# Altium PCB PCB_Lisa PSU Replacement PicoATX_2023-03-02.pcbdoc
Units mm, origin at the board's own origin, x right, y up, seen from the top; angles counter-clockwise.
Board outline 280.87 x 238.64 mm, 2 copper layers (Top Layer, Bottom Layer); 64 components, 40 nets, 167 pads, 1 vias.
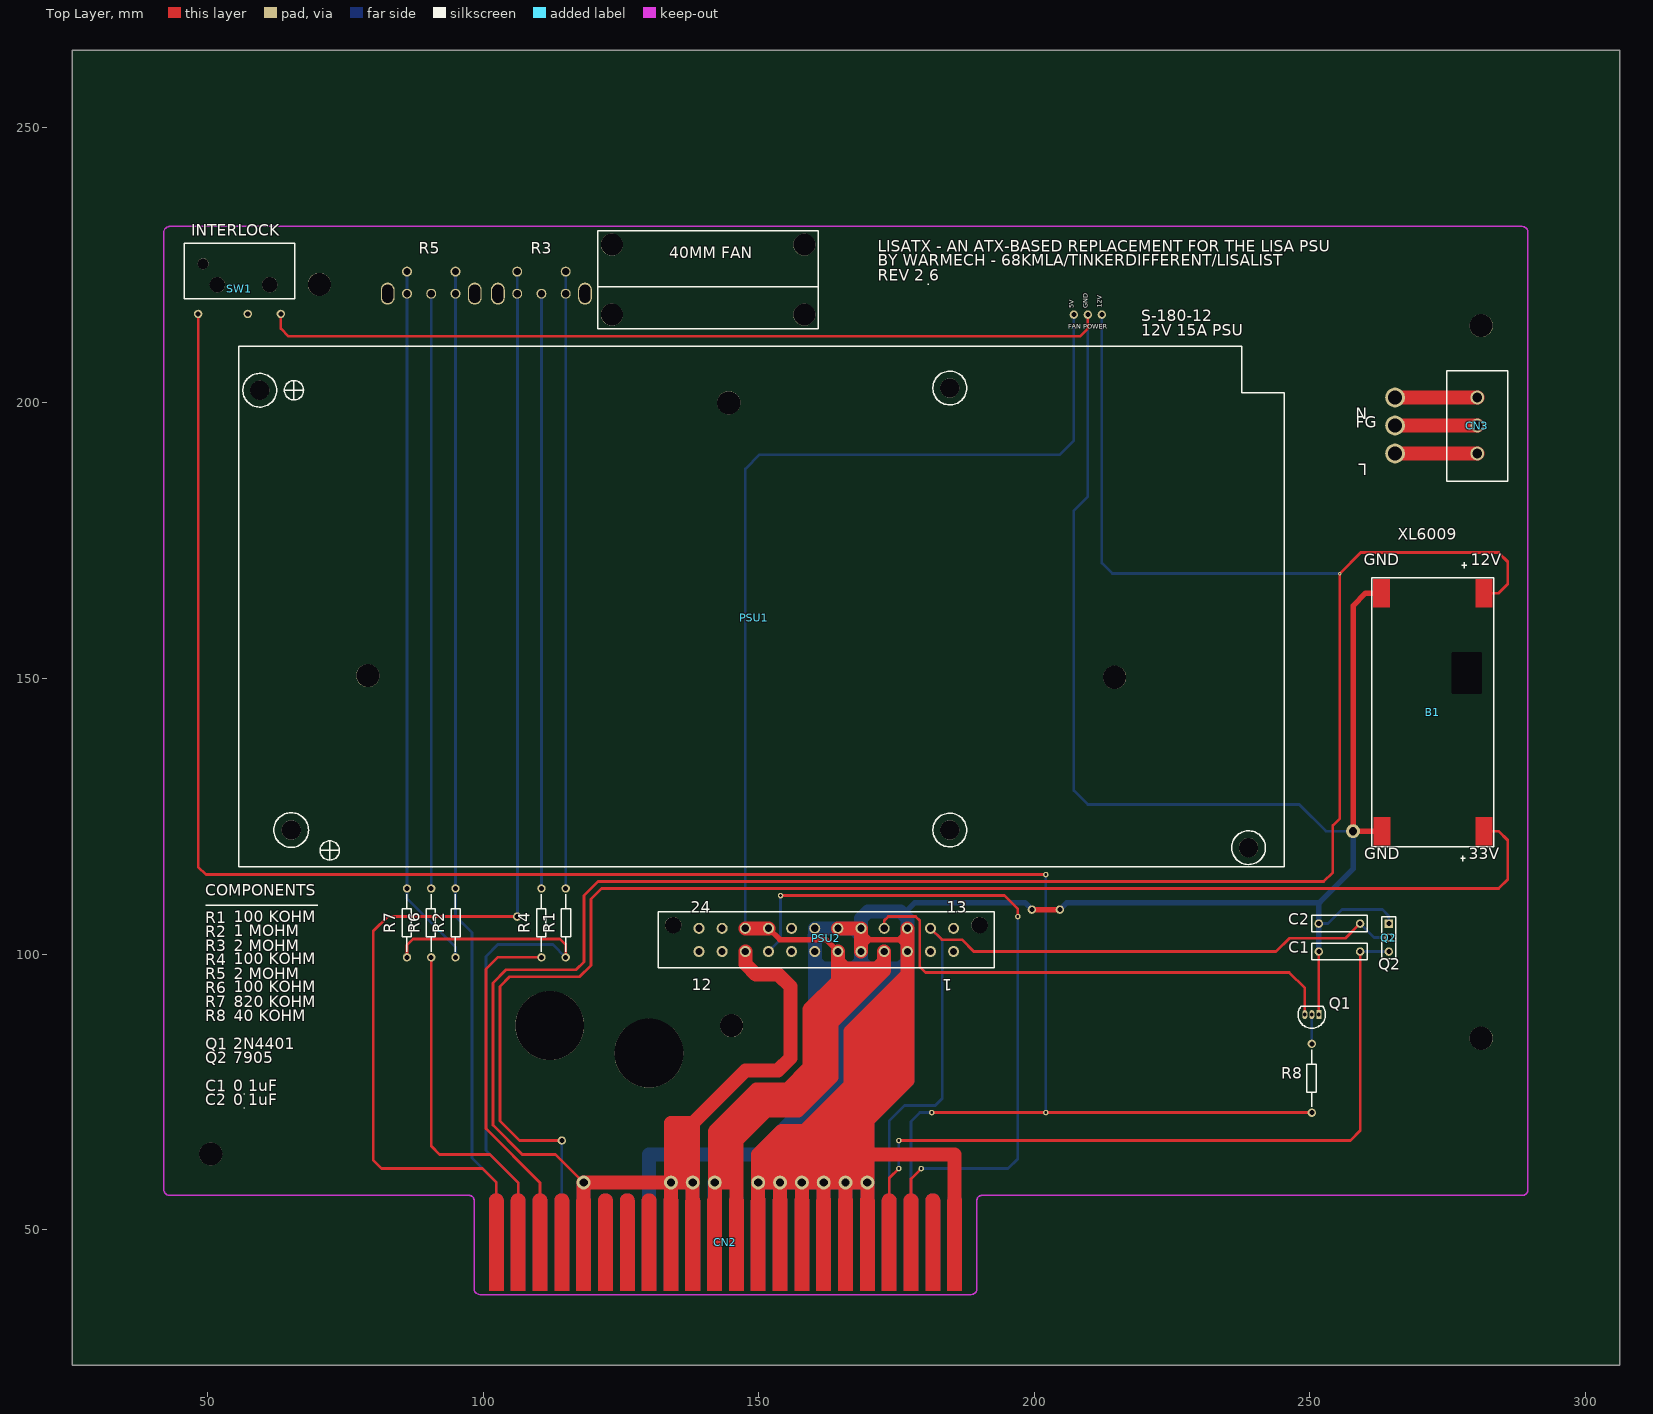
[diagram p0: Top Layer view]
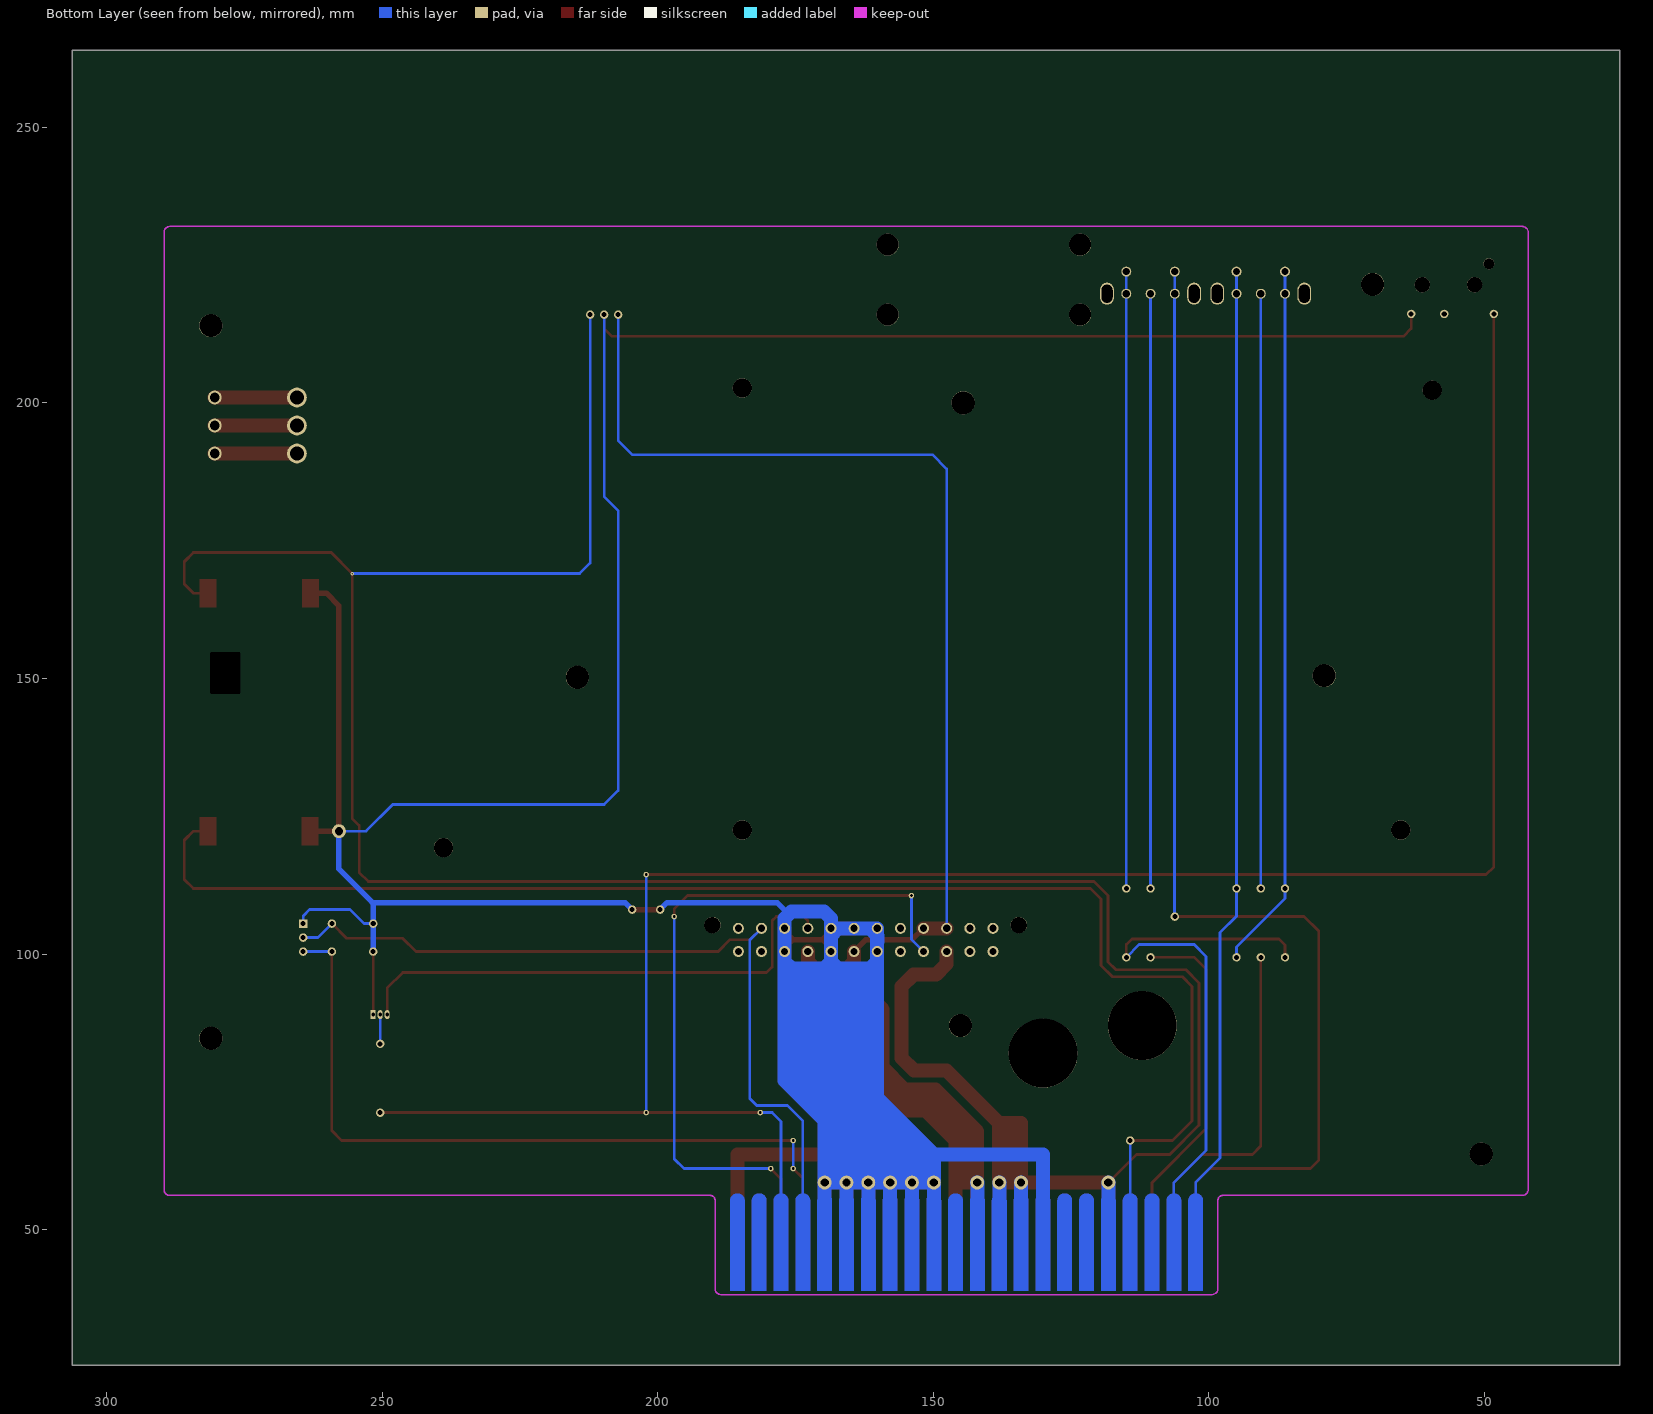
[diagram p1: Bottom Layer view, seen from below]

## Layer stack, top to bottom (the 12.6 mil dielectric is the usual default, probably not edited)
Top Layer: signal copper (thickness not stored)
Dielectric: dielectric 0.32, FR-4, Dk 4.8
Bottom Layer: signal copper (thickness not stored)

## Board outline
306.273,25.4 25.4,25.4 25.4,264.043 306.273,264.043

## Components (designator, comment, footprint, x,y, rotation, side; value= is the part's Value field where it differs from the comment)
B1 "XL6009_BOOSTER" XL6009_BOOSTER 261.531,168.021 r0 top
C1 "0.1uF" LISA_DISC_CERAMIC_CAPACITOR 255.435,100.457 r180 top
C2 "0.1uF" LISA_DISC_CERAMIC_CAPACITOR 255.308,105.537 r0 top
CN2 "EDGE CONNECTOR" LISA_PSU_EDGE_CONNECTOR 101.07,38.927 r0 top
CN3 "AC IN" LISA_PSU_AC_IN 280.375,195.907 r90 top
PSU1 "PSU_S-180-12" PSU_S-180-12 55.664,210.312 r0 top
PSU2 "PICO_ATX_5V8A" PICO_ATX_5V8A 162.267,102.577 r0 top
Q1 "2N4401" TO-92-3_L4.9-W3.7-P1.27-L 250.355,89.027 r180 top
Q2 "7905" TO-220 264.325,102.996 r270 top
R1 "100K" LISA_RESISTOR 114.976,105.664 r270 top
R2 "1M" LISA_RESISTOR 94.974,105.664 r270 top
R3 "FOCUS" LISA_CRT_POT 110.576,221.826 r0 top
R4 "100K" LISA_RESISTOR 110.576,105.664 r90 top
R5 "BRIGHT" LISA_CRT_POT 90.574,221.826 r0 top
R6 "100K" LISA_RESISTOR 90.574,105.664 r90 top
R7 "820K" LISA_RESISTOR 86.174,105.664 r90 top
R8 "40K" LISA_RESISTOR 250.355,77.47 r90 top
SW1 "SAFETY_INTERLOCK" 111SM1_LEAF_SWITCH 48.298,216.154 r0 top
? "" ? 56.175,227.788 r0 top
? "" ? 75.089,226.779 r0 top
? "" ? 93.325,216.054 r0 top
? "" ? 149.134,216.029 r0 top
? "" ? 251.971,169.456 r0 top
? "" ? 217.464,191.129 r0 top
? "" ? 285.349,224.385 r0 top
? "" ? 275.107,223.029 r0 top
? "" ? 81.501,191.279 r0 top
? "" ? 60.575,147.222 r0 top
? "" ? 46.325,63.901 r0 top
? "" ? 55.751,60.011 r0 top
? "" ? 285.349,64.146 r0 top
? "" ? 277.119,70.511 r0 top
? "" ? 185.121,159.529 r0 top
? "" ? 93.575,84.758 r0 top
? "" ? 87.075,80.072 r0 top
? "" ? 77.075,89.228 r0 top
? "" ? 135.002,157.029 r0 top
? "" ? 130.299,159.529 r0 top
? "" ? 86.756,227.929 r0 top
? "" ? 66.325,224.154 r0 top
? "" ? 76.325,221.454 r0 top
? "" ? 59.398,69.469 r0 top
? "" ? 155.187,219.529 r0 top
? "" ? 216.804,110.707 r0 top
? "" ? 220.465,130.072 r0 top
? "" ? 236.198,128.956 r0 top
? "" ? 229.928,119.323 r0 top
? "" ? 213.954,92.404 r0 top
? "" ? 210.965,99.379 r0 top
? "" ? 241.516,126.706 r0 top
? "" ? 245.263,123.207 r0 top
? "" ? 230.177,111.089 r0 top
? "" ? 227.678,108.883 r0 top
? "" ? 134.713,226.03 r0 top
? "" ? 140.815,219.975 r0 top
? "" ? 119.662,216.058 r0 top
? "" ? 125.815,226.168 r0 top
? "" ? 155.82,225.543 r0 top
? "" ? 136.59,228.529 r0 top
? "" ? 126.428,231.139 r0 top
? "" ? 120.942,237.834 r0 top
? "" ? 160.693,234.403 r0 top
? "" ? 122.191,240.327 r0 top
? "" ? 117.071,228.642 r0 top

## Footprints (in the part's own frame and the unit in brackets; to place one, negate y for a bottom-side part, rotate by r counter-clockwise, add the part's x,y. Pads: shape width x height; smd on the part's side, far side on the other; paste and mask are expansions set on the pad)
111SM1_LEAF_SWITCH [mil]
  round 60 hole 36: 1(-0.55,0) 2(353.78,0) 3(590,0)
  round 78.74 hole 78.74 unplated: ""(34.88,358.27)
  round 110.24 hole 110.24 unplated: ""(137.24,208.66) ""(511.26,208.66)
  silkscreen extent -99,110 689,504
LISA_CRT_POT [mm]
  round 1.8 hole 1.3: 1(-4.4,2) 2(0,-2) 3(4.4,2)
LISA_DISC_CERAMIC_CAPACITOR [mil]
  round 60 hole 36: 1(-145.27,0) 2(150,0)
  silkscreen extent -195,-60 200,60
LISA_PSU_AC_IN [mm]
  round 2.5 hole 1.8: 1(-5.08,0) 2(0,0) 3(5.08,0)
LISA_PSU_EDGE_CONNECTOR [mm]
  round 0 smd: 1(1.32,8.81) 2(5.28,8.81) 3(9.24,8.81) 4(13.2,8.81) 5(17.16,8.81) 6(21.12,8.81) 7(25.08,8.81) 8(29.04,8.81) 9(33,8.81) 10(36.96,8.81) 11(40.92,8.81) 12(44.88,8.81) 13(48.84,8.81) 14(52.8,8.81) 15(56.76,8.81) 16(60.72,8.81) 17(64.68,8.81) 18(68.64,8.81) 19(72.6,8.81) 20(76.56,8.81) 21(80.52,8.81) 22(84.48,8.81)
  round 0 smd far side: A(1.32,8.81) B(5.28,8.81) C(9.24,8.81) D(13.2,8.81) E(17.16,8.81) F(21.12,8.81) H(25.08,8.81) J(29.04,8.81) K(33,8.81) L(36.96,8.81) M(40.92,8.81) N(44.88,8.81) P(48.84,8.81) R(52.8,8.81) S(56.76,8.81) T(60.72,8.81) U(64.68,8.81) V(68.64,8.81) W(72.6,8.81) X(76.56,8.81) Y(80.52,8.81) Z(84.48,8.81)
  Top Layer region: 338 vertices and 0 holes, not listed, extent 3.96,0 6.6,17.62
  Top Layer region: 338 vertices and 0 holes, not listed, extent 0,0 2.64,17.62
  Top Layer region: 338 vertices and 0 holes, not listed, extent 7.92,0 10.56,17.62
  Top Layer region: 338 vertices and 0 holes, not listed, extent 11.88,0 14.52,17.62
  Top Layer region: 338 vertices and 0 holes, not listed, extent 15.84,0 18.48,17.62
  Top Layer region: 338 vertices and 0 holes, not listed, extent 19.8,0 22.44,17.62
  Top Layer region: 338 vertices and 0 holes, not listed, extent 23.76,0 26.4,17.62
  Top Layer region: 338 vertices and 0 holes, not listed, extent 27.72,0 30.36,17.62
  Top Layer region: 338 vertices and 0 holes, not listed, extent 31.68,0 34.32,17.62
  Top Layer region: 338 vertices and 0 holes, not listed, extent 35.64,0 38.28,17.62
  Top Layer region: 338 vertices and 0 holes, not listed, extent 39.6,0 42.24,17.62
  Top Layer region: 338 vertices and 0 holes, not listed, extent 43.56,0 46.2,17.62
  Top Layer region: 338 vertices and 0 holes, not listed, extent 47.52,0 50.16,17.62
  Top Layer region: 338 vertices and 0 holes, not listed, extent 51.48,0 54.12,17.62
  Top Layer region: 338 vertices and 0 holes, not listed, extent 55.44,0 58.08,17.62
  Top Layer region: 338 vertices and 0 holes, not listed, extent 59.4,0 62.04,17.62
  Top Layer region: 338 vertices and 0 holes, not listed, extent 63.36,0 66,17.62
  Top Layer region: 338 vertices and 0 holes, not listed, extent 67.32,0 69.96,17.62
  Top Layer region: 338 vertices and 0 holes, not listed, extent 71.28,0 73.92,17.62
  Top Layer region: 338 vertices and 0 holes, not listed, extent 75.24,0 77.88,17.62
  Top Layer region: 338 vertices and 0 holes, not listed, extent 79.2,0 81.84,17.62
  Top Layer region: 338 vertices and 0 holes, not listed, extent 83.16,0 85.8,17.62
  Bottom Layer region: 338 vertices and 0 holes, not listed, extent 83.16,0 85.8,17.62
  Bottom Layer region: 338 vertices and 0 holes, not listed, extent 79.2,0 81.84,17.62
  Bottom Layer region: 338 vertices and 0 holes, not listed, extent 75.24,0 77.88,17.62
  Bottom Layer region: 338 vertices and 0 holes, not listed, extent 71.28,0 73.92,17.62
  Bottom Layer region: 338 vertices and 0 holes, not listed, extent 67.32,0 69.96,17.62
  Bottom Layer region: 338 vertices and 0 holes, not listed, extent 63.36,0 66,17.62
  Bottom Layer region: 338 vertices and 0 holes, not listed, extent 59.4,0 62.04,17.62
  Bottom Layer region: 338 vertices and 0 holes, not listed, extent 55.44,0 58.08,17.62
  Bottom Layer region: 338 vertices and 0 holes, not listed, extent 51.48,0 54.12,17.62
  Bottom Layer region: 338 vertices and 0 holes, not listed, extent 47.52,0 50.16,17.62
  Bottom Layer region: 338 vertices and 0 holes, not listed, extent 43.56,0 46.2,17.62
  Bottom Layer region: 338 vertices and 0 holes, not listed, extent 39.6,0 42.24,17.62
  Bottom Layer region: 338 vertices and 0 holes, not listed, extent 35.64,0 38.28,17.62
  Bottom Layer region: 338 vertices and 0 holes, not listed, extent 31.68,0 34.32,17.62
  Bottom Layer region: 338 vertices and 0 holes, not listed, extent 27.72,0 30.36,17.62
  Bottom Layer region: 338 vertices and 0 holes, not listed, extent 23.76,0 26.4,17.62
  Bottom Layer region: 338 vertices and 0 holes, not listed, extent 19.8,0 22.44,17.62
  Bottom Layer region: 338 vertices and 0 holes, not listed, extent 15.84,0 18.48,17.62
  Bottom Layer region: 338 vertices and 0 holes, not listed, extent 11.88,0 14.52,17.62
  Bottom Layer region: 338 vertices and 0 holes, not listed, extent 7.92,0 10.56,17.62
  Bottom Layer region: 338 vertices and 0 holes, not listed, extent 0,0 2.64,17.62
  Bottom Layer region: 338 vertices and 0 holes, not listed, extent 3.96,0 6.6,17.62
LISA_RESISTOR [mil]
  round 60 hole 36: 1(-246.06,0) 2(246.06,0)
  silkscreen extent -205,-30 205,35
PICO_ATX_5V8A [mm]
  round 2 hole 1.3: 1(23.1,-2.1) 2(18.9,-2.1) 3(14.7,-2.1) 4(10.5,-2.1) 5(6.3,-2.1) 6(2.1,-2.1) 7(-2.1,-2.1) 8(-6.3,-2.1) 9(-10.5,-2.1) 10(-14.7,-2.1) 11(-18.9,-2.1) 12(-23.1,-2.1) 13(23.1,2.1) 14(18.9,2.1) 15(14.7,2.1) 16(10.5,2.1) 17(6.3,2.1) 18(2.1,2.1) 19(-2.1,2.1) 20(-6.3,2.1) 21(-10.5,2.1) 22(-14.7,2.1) 23(-18.9,2.1) 24(-23.1,2.1)
  round 3 hole 3 unplated: ""(-27.8,2.7) ""(27.8,2.7)
  silkscreen extent -30.48,-5.08 30.48,5.08
PSU_S-180-12 [mm]
  round 3.5 hole 3.5 unplated: ""(3.8,-8) ""(9.5,-87.8) ""(129,-87.8) ""(129,-7.6) ""(183.2,-91)
  silkscreen extent 0,-94.5 189.7,0
TO-92-3_L4.9-W3.7-P1.27-L [mm]
  rect 0.9x1.6 hole 0.7: 1(-1.27,0)
  oval 0.9x1.6 hole 0.7: 2(0,0) 3(1.27,0)
  silkscreen extent -2.48,-1.5 2.48,2.48
TO-220 [mil]
  rect 60x60 hole 36: 1(-100,0)
  round 60 hole 36: 2(0,0) 3(100,0)
  silkscreen extent -150,-50 150,50
XL6009_BOOSTER [mm]
  round 0 smd: 1(1.496,-2.536) 2(20.038,-2.536) 3(1.52,-45.716) 4(20.038,-45.716)
  Top Layer region: -0.004,0.004 -0.004,-5.076 2.996,-5.076 2.996,0.004
  Top Layer region: 18.538,0.004 18.538,-5.076 21.538,-5.076 21.538,0.004
  Top Layer region: 0.02,-43.176 0.02,-48.256 3.02,-48.256 3.02,-43.176
  Top Layer region: 18.538,-43.176 18.538,-48.256 21.538,-48.256 21.538,-43.176
  Multi-Layer board cut-out: 19.677,-20.57 19.658,-20.666 19.604,-20.747 19.523,-20.801 19.427,-20.82 19.427,-20.82 19.427,-20.82 14.474,-20.82 14.378,-20.801 14.297,-20.747 14.243,-20.666 14.224,-20.57 14.224,-20.57 14.224,-13.458 14.224,-13.458 14.258,-13.333 14.349,-13.242 14.474,-13.208 14.474,-13.208 14.474,-13.208 19.427,-13.208 19.427,-13.208 19.552,-13.242 19.644,-13.333 19.677,-13.458 19.677,-13.458 19.677,-13.458 19.677,-20.57 19.677,-20.57
  silkscreen extent -0.25,-51.18 21.84,3.05
? [mm]

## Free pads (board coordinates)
  round 1.8 hole 1.3: 1(86.174,219.826) 1(106.176,219.826) 3(94.974,219.826) 3(114.976,219.826)
  round 3.6 hole 2.5: 1(265.468,190.828) 2(265.468,195.908) 3(265.468,200.988)
  round 2.54 hole 1.5: 23(118.229,58.547) 23(134.07,58.547) 23(138.03,58.547) 23(142.024,58.547) 23(149.911,58.547) 23(153.87,58.547) 23(157.83,58.547) 23(161.79,58.547) 23(165.75,58.547) 23(169.71,58.547) 23(257.848,122.301)
  oval 2.5x4 hole 2 slot 3.3 at 90 deg: 28(118.476,219.826) 29(102.676,219.826) 30(98.474,219.826) 31(82.674,219.826)
  round 1.524 hole 0.914: 34(212.255,216.027) 35(209.715,216.027) 36(207.175,216.027) 37(199.555,108.077) 38(204.635,108.077) 40(114.27,66.167) +33V(106.176,106.807)
  round 1 hole 0.5: 42(202.095,114.427) 43(197.015,106.807) 44(175.425,61.087) 45(179.489,61.087) 46(175.425,66.167) 47(181.394,71.247) 47(202.095,71.247) 48(153.962,110.617)
  round 4.2 hole 4.2 unplated: ""(50.575,63.727) ""(70.275,221.527) ""(79.075,150.527) ""(144.575,200.027) ""(145.075,87.027) ""(214.575,150.227) ""(281.075,84.727) ""(281.075,214.027)
  round 12.5 hole 12.5 unplated: ""(112.075,87.027) ""(130.075,82.027)
  round 4 hole 4 unplated: ""(123.355,216.027) ""(123.355,228.727) ""(158.28,216.027) ""(158.28,228.727)

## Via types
v1: diameter 0.61, hole 0.305, Top Layer to Bottom Layer, tented both sides, 1 vias

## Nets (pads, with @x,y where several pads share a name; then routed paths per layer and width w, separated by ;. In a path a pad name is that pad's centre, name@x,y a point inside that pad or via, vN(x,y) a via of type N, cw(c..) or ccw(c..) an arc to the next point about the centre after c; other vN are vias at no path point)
+5V: CN2.11 CN2.12 CN2.M pad.23@142.024,58.547 pad.36 PSU2.4 PSU2.6 PSU2.21 PSU2.22 | length 350.7
  Top Layer w1: PSU2.21 153.827,102.616 162.227,102.616 PSU2.6
  Top Layer w2.54: CN2.11 142.024,47.77 pad.23@142.024,58.547 ; CN2.12 145.951,58.541 ; PSU2.22 PSU2.21 ; pad.23@142.024,58.547 145.951,58.542 145.951,66.167 ; pad.23@142.024,58.547 142.024,66.167 ; 142.024,66.167 142.024,67.818 149.601,75.395 155.189,75.395 159.169,79.375 159.169,89.916 164.366,95.113 PSU2.6 164.366,98.689 165.646,97.409 171.488,97.409 172.768,98.689 172.768,100.477 172.768,97.038 163.233,87.503 163.233,77.724 157.137,71.628 151.412,71.628 145.951,66.167 ; 142.024,66.167 145.951,66.167
  Bottom Layer w0.5: PSU2.22 147.567,188.042 150.152,190.627 204.635,190.627 207.175,193.167 pad.36
  Bottom Layer w2.54: CN2.M 141.99,58.513 pad.23@142.024,58.547
+5VSB: CN2.20 pad.43 pad.45 pad.48 PSU2.9 | length 132.8
  Top Layer w0.5: pad.48 194.602,110.617 197.015,108.204 pad.43 ; CN2.20 177.63,59.228 179.235,60.833 pad.45
  Bottom Layer w0.5: PSU2.9 153.962,102.672 pad.48 ; pad.45 195.237,61.087 197.015,62.865 pad.43
+12V: B1.2 CN2.5 CN2.9 CN2.10 CN2.E CN2.K CN2.L pad.23@118.229,58.547 pad.23@134.07,58.547 pad.23@138.03,58.547 pad.34 PSU2.10 | length 557.9
  Top Layer w0.5: pad.23@118.229,58.547 113.149,63.627 107.099,63.627 101.765,68.961 101.765,94.742 104.178,97.155 116.878,97.155 118.275,98.552 118.275,110.617 120.815,113.157 252.514,113.157 254.165,114.808 254.165,123.317 255.435,124.587 v1(255.435,169.037) 259.245,172.847 284.264,172.847 285.915,171.196 285.915,167.132 284.267,165.484 B1.2
  Top Layer w2.54: CN2.5 118.229,58.547 pad.23@134.069,58.547 ; CN2.9 pad.23@134.07,58.547 ; pad.23@138.029,58.547 138.087,58.547 138.087,69.342 ; CN2.10 138.03,58.547 pad.23@134.07,58.547 ; PSU2.10 147.566,98.217 149.527,96.256 153.591,96.256 155.74,94.107 155.74,81.153 153.454,78.867 147.612,78.867 138.087,69.342 ; pad.23@134.07,58.547 134.07,69.342 138.087,69.342
  Bottom Layer w0.5: pad.34 212.255,170.942 214.16,169.037 v1(255.435,169.037)
  Bottom Layer w2.54: CN2.E pad.23@118.229,58.547 ; CN2.K pad.23@134.07,58.547 ; CN2.L pad.23@138.03,58.547
+33V: B1.4 CN2.D pad.40 | length 265.7
  Top Layer w0.5: pad.40 106.591,66.167 103.035,69.723 103.035,94.107 104.813,95.885 117.513,95.885 119.545,97.917 119.545,109.982 121.45,111.887 284.264,111.887 285.915,113.538 285.915,120.65 284.262,122.301 281.569,122.301
  Bottom Layer w0.5: CN2.D pad.40
+300V: CN2.1 pad.1@106.176,219.826 pad.+33V R3.1 | length 220.7
  Top Layer w0.5: CN2.1 102.39,58.557 99.86,61.087 81.572,61.087 80.048,62.611 80.048,104.14 82.715,106.807 pad.+33V@106.21,106.807
  Bottom Layer w0.5: pad.1@106.176,219.826 106.21,219.792 pad.+33V@106.21,106.807 ; pad.1@106.177,219.827 R3.1
-5V: C1.1 CN2.19 pad.44 pad.46 Q2.3 | length 141.3
  Top Layer w0.5: CN2.19 173.67,59.332 pad.44 ; pad.46 257.34,66.167 259.126,67.953 C1.1
  Bottom Layer w0.5: pad.44 pad.46 ; C1.1 Q2.3
-12V: C2.2 CN2.W PSU2.14 Q2.2 | length 153.1
  Top Layer w0.5: PSU2.14 183.228,102.616 186.855,102.616 189.014,100.457 243.878,100.457 246.291,102.87 256.451,102.87 C2.2
  Bottom Layer w0.5: CN2.W 173.67,69.746 176.441,72.517 182.029,72.517 183.299,73.787 183.299,102.545 PSU2.14 ; C2.2 261.659,102.996 Q2.2
-100V: CN2.B R1.2 R7.1 | length 104.8
  Top Layer w0.5: R7.1 86.175,101.63 87.287,102.743 113.957,102.743 114.976,101.724 R1.2
  Bottom Layer w0.5: CN2.B 106.35,58.534 100.495,64.389 100.495,99.568 102.654,101.727 112.664,101.727 R1.2
BRIGHT: CN2.2 R6.1 | length 63.6
  Top Layer w0.5: R6.1 90.574,65.166 92.113,63.627 101.257,63.627 106.35,58.534 CN2.2
BRTRET: CN2.A pad.3@94.974,219.826 R2.1 R5.3 | length 179.2
  Bottom Layer w0.5: R2.1 94.973,106.868 97.955,103.886 97.955,62.992 102.39,58.557 CN2.A ; R2.1 94.974,219.826 R5.3
FG: CN3.2 pad.2 | length 14.9
  Top Layer w2.54: pad.2 CN3.2
FOCUS: CN2.3 R4.1 | length 64.6
  Top Layer w0.5: CN2.3 110.31,58.511 100.495,68.326 100.495,97.282 102.626,99.413 R4.1
GND: B1.1 B1.3 C1.2 C2.1 CN2.13 CN2.14 CN2.15 CN2.16 CN2.17 CN2.18 CN2.22 CN2.J CN2.P CN2.R CN2.S CN2.T CN2.U CN2.V pad.23@149.911,58.547 pad.23@153.87,58.547 pad.23@157.83,58.547 pad.23@161.79,58.547 pad.23@165.75,58.547 pad.23@169.71,58.547 pad.23@257.848,122.301 pad.35 pad.37 pad.38 PSU2.3 PSU2.5 PSU2.7 PSU2.15 PSU2.17 PSU2.18 PSU2.19 Q1.1 Q2.1 SW1.3 | length 1038.8
  Top Layer w0.5: SW1.3 63.284,213.487 64.681,212.09 208.318,212.09 209.715,213.487 pad.35 ; Q1.1 C1.2
  Top Layer w1: PSU2.5 168.567,101.092 170.091,102.616 ; 168.567,102.616 170.627,102.616 176.967,102.616 ; PSU2.17 168.567,104.14 170.091,102.616 ; PSU2.3 176.967,101.074 175.425,102.616 ; PSU2.15 176.967,104.158 175.425,102.616 ; pad.37 pad.38 ; B1.1 260.137,165.484 257.848,163.195 257.848,122.301 257.852,122.305 B1.3 ; 170.091,102.616 171.615,102.616 170.091,102.616 ; 175.425,102.616 173.919,102.616 175.425,102.616
  Top Layer w2.54: CN2.13 pad.23@149.911,58.547 ; CN2.14 pad.23@153.87,58.547 ; CN2.15 pad.23@157.83,58.547 ; CN2.16 pad.23@161.79,58.547 ; PSU2.18 PSU2.17 PSU2.5 ; CN2.17 pad.23@165.75,58.547 ; CN2.18 pad.23@169.71,58.547 ; PSU2.15 PSU2.3 ; CN2.22 185.55,63.627 169.71,63.627 ; pad.23@149.911,58.547 pad.23@169.71,58.547 ; pad.23@149.911,58.547 149.911,63.627 ; 149.911,63.627 154.229,67.945 158.407,67.945 166.662,76.2 166.662,85.979 176.967,96.284 PSU2.3 ; 149.911,63.627 169.71,63.627 ; pad.23@169.71,58.547 169.71,63.627 ; 169.71,63.627 169.71,69.85 176.967,77.107 PSU2.3
  Bottom Layer w0.5: pad.35 209.715,183.007 207.175,180.467 207.175,129.667 209.715,127.127 248.069,127.127 252.895,122.301 pad.23@257.848,122.301 ; C2.1 253.276,105.537 255.816,108.077 263.182,108.077 264.325,106.934 Q2.1
  Bottom Layer w1: PSU2.15 176.967,107.968 178.346,109.347 198.285,109.347 pad.37 ; pad.38 205.905,109.347 251.752,109.347 257.848,115.443 pad.23@257.848,122.301 ; C2.1 C1.2 ; C2.1 251.618,109.347
  Bottom Layer w2.54: CN2.J 130.109,63.627 149.911,63.627 ; CN2.P pad.23@149.911,58.547 ; CN2.R pad.23@153.87,58.547 ; CN2.S pad.23@157.83,58.547 ; CN2.T pad.23@161.79,58.547 ; PSU2.18 161.45,104.651 160.142,103.322 PSU2.7 ; PSU2.18@164.368,104.676 167.284,104.65 168.592,103.322 PSU2.5 ; CN2.U pad.23@165.75,58.547 ; CN2.V pad.23@169.71,58.547 ; pad.23@149.911,58.547 149.911,63.627 ; pad.23@149.911,58.547 pad.23@169.71,58.547 ; 149.911,63.627 160.167,73.884 PSU2.7 ; PSU2.7 PSU2.19 PSU2.18 PSU2.17 ; PSU2.7 160.167,98.679 161.437,97.409 167.279,97.409 168.567,98.697 PSU2.5 ; PSU2.5 168.567,98.679 169.837,97.409 175.679,97.409 176.967,98.697 PSU2.3 ; PSU2.5 PSU2.17 ; PSU2.17 168.567,106.457 169.855,107.745 175.697,107.745 176.967,106.475 PSU2.15 PSU2.3 ; pad.23@169.71,58.547 169.71,63.627 169.71,69.85 176.967,77.107 PSU2.3
LIVE: CN3.1 pad.1@265.468,190.828 | length 14.9
  Top Layer w2.54: pad.1@265.468,190.828 CN3.1
NEUTRAL: CN3.3 pad.3@265.468,200.988 | length 14.9
  Top Layer w2.54: pad.3@265.468,200.988 CN3.3
ON/OFF: CN2.X pad.42 pad.47 R8.1 SW1.1 | length 393.2
  Top Layer w0.5: SW1.1 48.285,115.837 49.695,114.427 pad.42 ; pad.47@181.394,71.247 250.355,71.247 R8.1
  Bottom Layer w0.5: CN2.X 177.63,69.642 179.235,71.247 pad.47@181.394,71.247 ; pad.47@202.095,71.247 pad.42
PS_ON: PSU2.16 Q1.3 | length 93.1
  Top Layer w0.5: PSU2.16@172.768,104.676 172.768,106.055 173.52,106.807 178.473,106.807 179.235,106.045 179.235,97.663 180.251,96.647 246.253,96.647 249.085,93.815 Q1.3
Q1_2: Q1.2 R8.2 | length 5.3
  Bottom Layer w0.5: R8.2 Q1.2
R1_1: pad.3@114.976,219.826 R1.1 R3.3 | length 111.9
  Bottom Layer w0.5: R1.1 pad.3@114.976,219.826 ; pad.3@114.976,219.827 R3.3
R4_2: R3.2 R4.2 | length 107.9
  Bottom Layer w0.5: R4.2 R3.2
R5_1: pad.1@86.174,219.826 R2.2 R5.1 R7.2 | length 128.1
  Bottom Layer w0.5: R7.2 pad.1@86.174,219.826 ; R7.2 86.175,110.079 94.973,101.28 R2.2 ; pad.1@86.175,219.827 R5.1
R6_2: R5.2 R6.2 | length 107.9
  Bottom Layer w0.5: R6.2 R5.2
S$418: 
S$422: 
S$426: 
S$430: 
S$434: 
S$438: 
S$442: 
S$446: 
S$12357: 
S$12361: 
S$12371: 
S$12510: 
S$13313: 
S$22266: 
S$24419: 
S$24426: 
S$31447: 
SENSE: CN2.N
pads on no net: CN2.4 CN2.6 CN2.7 CN2.8 CN2.21 CN2.C CN2.F CN2.H CN2.Y CN2.Z PSU1. PSU2. PSU2.1 PSU2.2 PSU2.8 PSU2.11 PSU2.12 PSU2.13 PSU2.20 PSU2.23 PSU2.24 SW1. SW1.2

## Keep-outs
Keep-Out Layer:
  lines w0.254: 42.075,57.227 ccw(c43.075,57.227) 43.075,56.227 ; 42.075,231.027 cw(c43.075,231.027) 43.075,232.027 ; 97.375,56.227 cw(c97.375,55.227) 98.375,55.227 ; 98.375,39.227 ccw(c99.375,39.227) 99.375,38.227 ; 188.575,38.227 ccw(c188.575,39.227) 189.575,39.227 ; 189.575,55.227 cw(c190.575,55.227) 190.575,56.227 ; 288.575,56.227 ccw(c288.575,57.227) 289.575,57.227 ; 288.575,232.027 cw(c288.575,231.027) 289.575,231.027

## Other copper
Top Layer:
  region net GND: 176.967,95.849 166.916,85.799 166.916,75.819 159.042,67.945 154.216,67.945 152.057,65.786 149.898,63.627 169.71,63.627 169.71,69.977 171.361,71.501 177.076,77.089 176.967,95.849
  region net +12V: 134.07,58.547 138.03,58.547 138.03,68.396 138.087,68.453 134.07,68.453
  region net +5V: 142.024,58.547 142.024,67.818 149.601,75.395 155.189,75.395 159.169,79.375 159.169,89.916 164.366,95.113 164.366,97.155 172.651,97.155 172.768,97.038 163.233,87.503 163.233,77.724 157.137,71.628 151.412,71.628 145.951,66.167 145.951,58.542 142.029,58.542 142.024,58.547
  rectangle net GND: 149.898,58.547 169.71,63.627
Bottom Layer:
  region net GND: 149.911,58.547 149.911,63.627 160.167,73.883 160.167,98.679 161.437,97.409 167.279,97.409 168.567,98.697 168.567,98.679 169.837,97.409 176.949,97.409 176.949,86.868 176.967,84.981 176.949,76.962 169.837,69.85 169.71,58.547 149.911,58.547

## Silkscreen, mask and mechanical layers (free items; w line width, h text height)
Top Overlay:
  circle w0.254: c65.165,122.517 r3.144
  circle w0.254: c59.474,202.311 r3.059
  circle w0.254: c184.674,202.711 r3.059
  circle w0.254: c184.674,122.511 r3.059
  circle w0.254: c238.874,119.311 r3.059
  lines w0.254: 274.866,185.801 285.915,185.801 285.915,205.867 274.866,205.867 274.866,185.801
  lines w0.254 net S$12357: 120.815,219.202 120.815,231.267
  lines w0.254 net S$12361: 160.82,219.202 160.82,231.267
  lines w0.254 net S$12371: 120.815,219.202 120.815,213.487 160.82,213.487 160.82,219.202
  lines w0.254 net S$12510: 120.815,231.275 160.82,231.275
  lines w0.254 net S$13313: 120.815,221.105 160.82,221.105
  lines w0.254 net S$22266: 180.759,221.488 180.759,221.615
  lines w0.254 net S$24419: 56.68,74.549 56.68,74.676
  lines w0.254 net S$24426: 56.68,72.009 56.68,72.136
  lines w0.254 net S$31447: 49.695,108.839 70.015,108.839
  text "INTERLOCK" at 47.028,229.616 h3.5
  text "LISATX - AN ATX-BASED REPLACEMENT FOR THE LISA PSU" at 171.615,226.695 h3.5
  text "40MM FAN" at 133.769,225.552 h3.5
  text "BY WARMECH - 68KMLA/TINKERDIFFERENT/LISALIST" at 171.615,224.155 h3.5
  text "REV 2 6" at 171.615,221.488 h3.5
  text "12V" at 212.636,217.297 h1.5 r90
  text "5V" at 207.556,217.17 h1.5 r90
  text "GND" at 210.096,217.17 h1.5 r90
  text "S-180-12" at 219.367,214.122 h3.5
  text "FAN POWER" at 206.159,213.106 h1.5
  text "12V 15A PSU" at 219.367,211.455 h3.5
  text "N" at 260.388,199.898 h3.5 r180
  text "FG" at 258.356,194.818 h3.5
  text "L" at 260.388,189.738 h3.5 r180
  text "XL6009" at 265.976,174.498 h3.5
  text "COMPONENTS" at 49.568,109.855 h3.5
  text "100 KOHM" at 54.775,105.029 h3.5
  text "R1" at 49.568,104.902 h3.5
  text "1 MOHM" at 54.775,102.489 h3.5
  text "R2" at 49.568,102.362 h3.5
  text "R3" at 49.568,99.822 h3.5
  text "2 MOHM" at 54.775,99.822 h3.5
  text "100 KOHM" at 54.775,97.409 h3.5
  text "R4" at 49.568,97.282 h3.5
  text "Q2" at 262.438,96.393 h3.5
  text "R5" at 49.568,94.742 h3.5
  text "2 MOHM" at 54.775,94.742 h3.5
  text "100 KOHM" at 54.775,92.329 h3.5
  text "R6" at 49.568,92.202 h3.5
  text "R7" at 49.568,89.662 h3.5
  text "820 KOHM" at 54.775,89.662 h3.5
  text "R8" at 49.568,87.122 h3.5
  text "40 KOHM" at 54.775,87.122 h3.5
  text "Q1" at 49.568,82.042 h3.5 r359
  text "2N4401" at 54.648,82.042 h3.5
  text "Q2" at 49.568,79.502 h3.5
  text "7905" at 54.648,79.502 h3.5
  text "C1" at 49.568,74.422 h3.5 r359
  text "0 1uF" at 54.648,74.422 h3.5
  text "C2" at 49.568,71.882 h3.5
  text "0 1uF" at 54.648,71.882 h3.5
